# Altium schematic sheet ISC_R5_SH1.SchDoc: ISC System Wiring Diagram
size B; DrawnBy: Filiberto Clara; Engineer: Filiberto Clara; Organization: LIGO Laboratory; Address1: California Institute of Technology; Address2: Massachusetts Institute of Technology; SheetNumber: 19; SheetTotal: 37
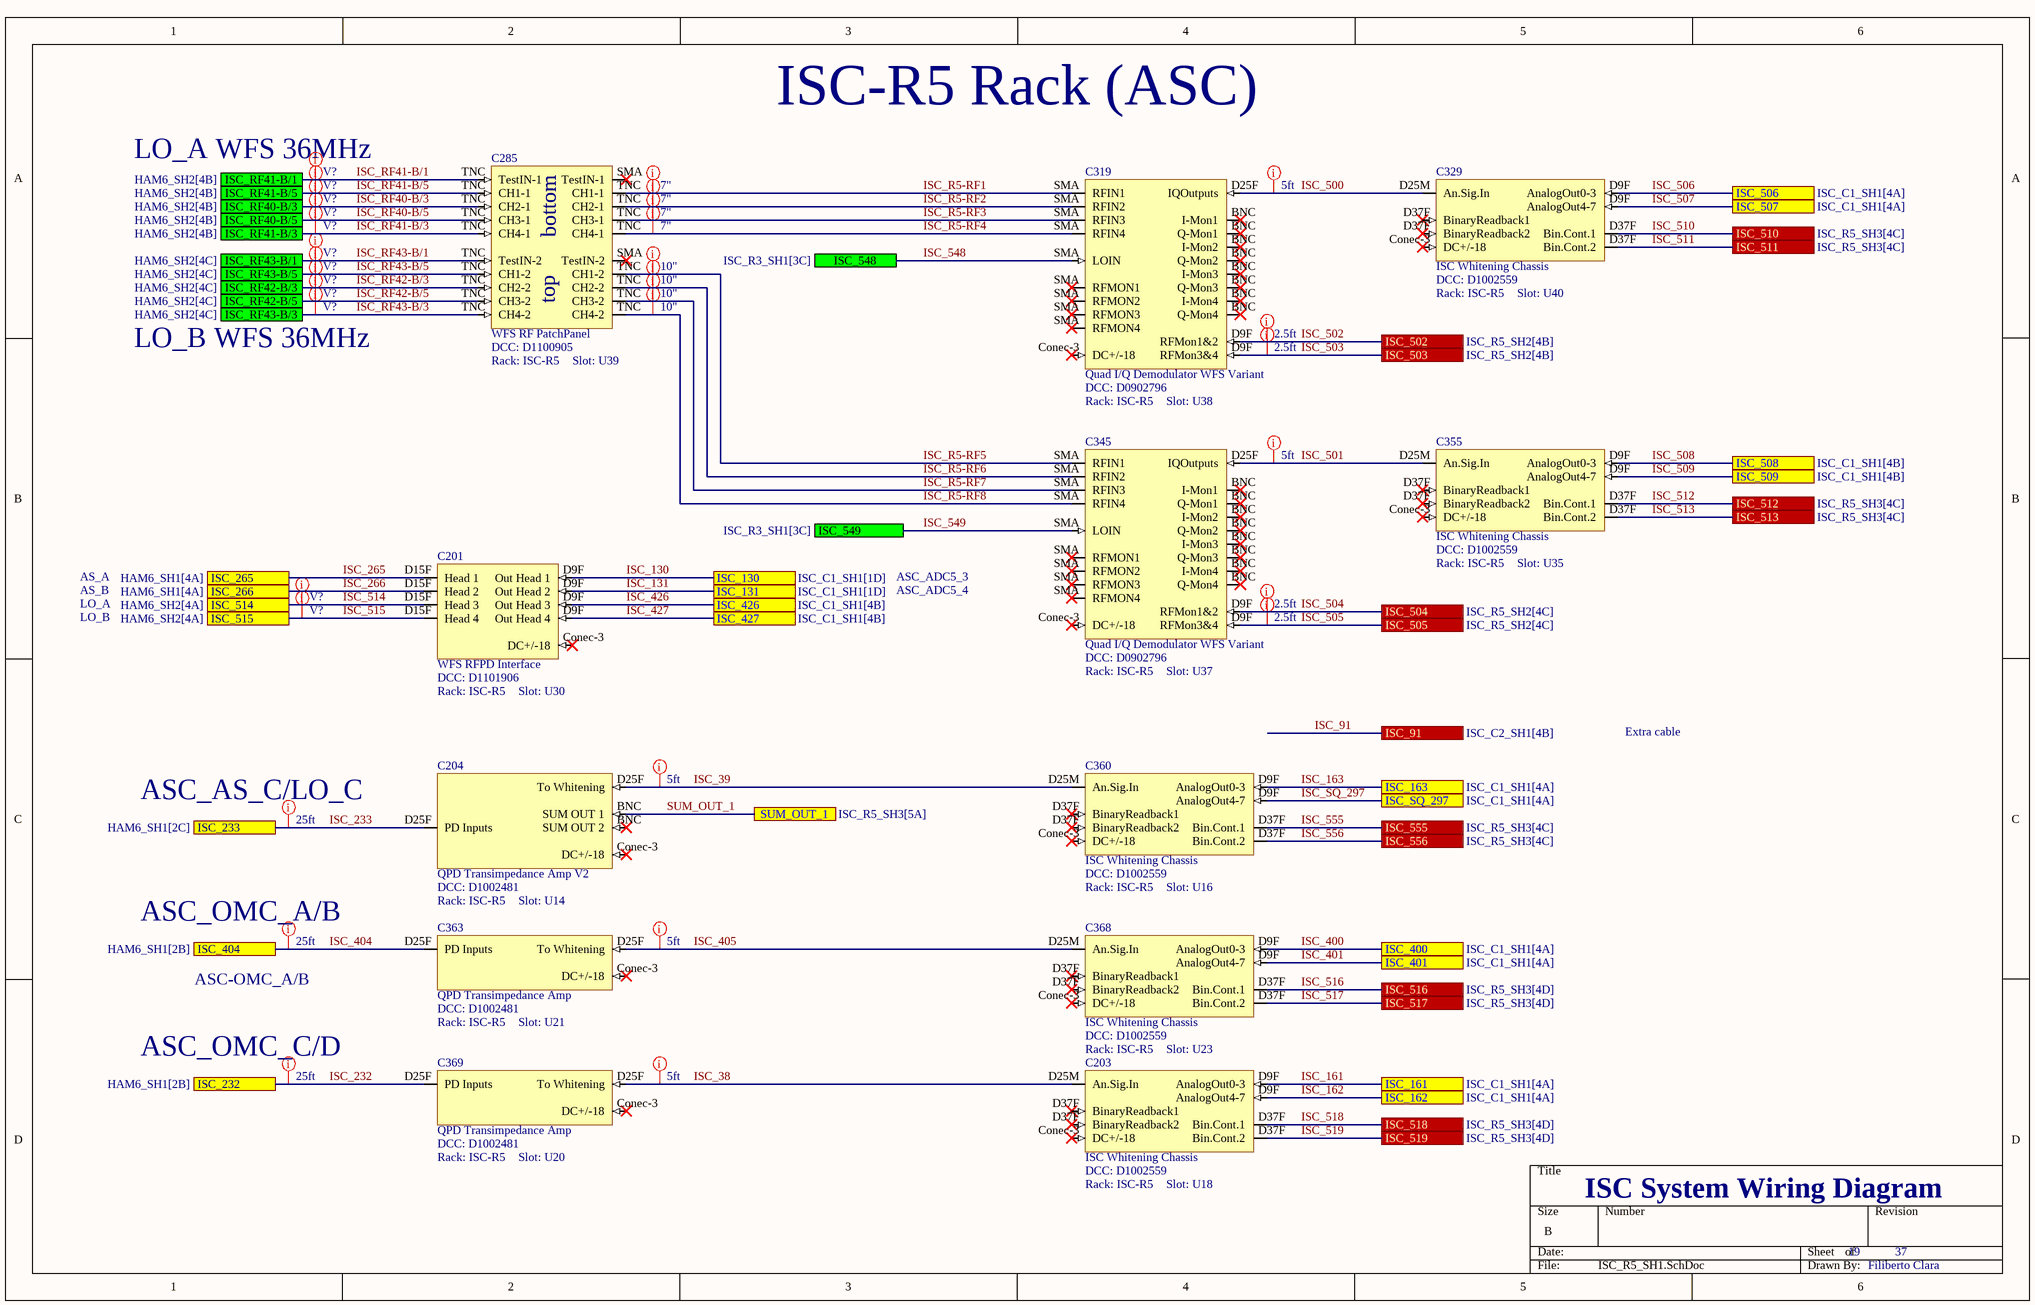
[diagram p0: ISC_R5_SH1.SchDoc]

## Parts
C201  WFS RFPD Interface  DCC: D1101906  Rack: ISC-R5  Slot: U30
C203  ISC Whitening Chassis  DCC: D1002559  Rack: ISC-R5  Slot: U18
C204  QPD Transimpedance Amp V2  DCC: D1002481  Rack: ISC-R5  Slot: U14
C285  WFS RF PatchPanel  DCC: D1100905  Rack: ISC-R5  Slot: U39
C319  Quad I/Q Demodulator WFS Variant  DCC: D0902796  Rack: ISC-R5  Slot: U38
C329  ISC Whitening Chassis  DCC: D1002559  Rack: ISC-R5  Slot: U40
C345  Quad I/Q Demodulator WFS Variant  DCC: D0902796  Rack: ISC-R5  Slot: U37
C355  ISC Whitening Chassis  DCC: D1002559  Rack: ISC-R5  Slot: U35
C360  ISC Whitening Chassis  DCC: D1002559  Rack: ISC-R5  Slot: U16
C363  QPD Transimpedance Amp  DCC: D1002481  Rack: ISC-R5  Slot: U21
C368  ISC Whitening Chassis  DCC: D1002559  Rack: ISC-R5  Slot: U23
C369  QPD Transimpedance Amp  DCC: D1002481  Rack: ISC-R5  Slot: U20

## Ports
ISC_91 (see ISC_C2_SH1[4B]), ISC_130 (see ISC_C1_SH1[1D]), ISC_131 (see ISC_C1_SH1[1D]), ISC_161 (see ISC_C1_SH1[4A]), ISC_162 (see ISC_C1_SH1[4A]), ISC_163 (see ISC_C1_SH1[4A]), ISC_232 (see HAM6_SH1[2B]), ISC_233 (see HAM6_SH1[2C]), ISC_265 (see HAM6_SH1[4A]), ISC_266 (see HAM6_SH1[4A]), ISC_400 (see ISC_C1_SH1[4A]), ISC_401 (see ISC_C1_SH1[4A]), ISC_404 (see HAM6_SH1[2B]), ISC_426 (see ISC_C1_SH1[4B]), ISC_427 (see ISC_C1_SH1[4B]), ISC_502 (see ISC_R5_SH2[4B]), ISC_503 (see ISC_R5_SH2[4B]), ISC_504 (see ISC_R5_SH2[4C]), ISC_505 (see ISC_R5_SH2[4C]), ISC_506 (see ISC_C1_SH1[4A]), ISC_507 (see ISC_C1_SH1[4A]), ISC_508 (see ISC_C1_SH1[4B]), ISC_509 (see ISC_C1_SH1[4B]), ISC_510 (see ISC_R5_SH3[4C]), ISC_511 (see ISC_R5_SH3[4C]), ISC_512 (see ISC_R5_SH3[4C]), ISC_513 (see ISC_R5_SH3[4C]), ISC_514 (see HAM6_SH2[4A]), ISC_515 (see HAM6_SH2[4A]), ISC_516 (see ISC_R5_SH3[4D]), ISC_517 (see ISC_R5_SH3[4D]), ISC_518 (see ISC_R5_SH3[4D]), ISC_519 (see ISC_R5_SH3[4D]), ISC_548 (see ISC_R3_SH1[3C]), ISC_549 (see ISC_R3_SH1[3C]), ISC_555 (see ISC_R5_SH3[4C]), ISC_556 (see ISC_R5_SH3[4C]), ISC_RF40-B/3 (see HAM6_SH2[4B]), ISC_RF40-B/5 (see HAM6_SH2[4B]), ISC_RF41-B/1 (see HAM6_SH2[4B]), ISC_RF41-B/3 (see HAM6_SH2[4B]), ISC_RF41-B/5 (see HAM6_SH2[4B]), ISC_RF42-B/3 (see HAM6_SH2[4C]), ISC_RF42-B/5 (see HAM6_SH2[4C]), ISC_RF43-B/1 (see HAM6_SH2[4C]), ISC_RF43-B/3 (see HAM6_SH2[4C]), ISC_RF43-B/5 (see HAM6_SH2[4C]), ISC_SQ_297 (see ISC_C1_SH1[4A]), SUM_OUT_1 (see ISC_R5_SH3[5A])

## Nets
ISC_38: C203.D25M(An.Sig.In) C369.D25F(To_Whitening)
ISC_39: C204.D25F(To_Whitening) C360.D25M(An.Sig.In)
ISC_130: C201.D9F(Out_Head_1) ; port ISC_130
ISC_131: C201.D9F(Out_Head_2) ; port ISC_131
ISC_161: C203.D9F(AnalogOut0-3) ; port ISC_161
ISC_162: C203.D9F(AnalogOut4-7) ; port ISC_162
ISC_163: C360.D9F(AnalogOut0-3) ; port ISC_163
ISC_232: C369.D25F(PD_Inputs) ; port ISC_232
ISC_233: C204.D25F(PD_Inputs) ; port ISC_233
ISC_265: C201.D15F(Head_1) ; port ISC_265
ISC_266: C201.D15F(Head_2) ; port ISC_266
ISC_400: C368.D9F(AnalogOut0-3) ; port ISC_400
ISC_401: C368.D9F(AnalogOut4-7) ; port ISC_401
ISC_404: C363.D25F(PD_Inputs) ; port ISC_404
ISC_405: C363.D25F(To_Whitening) C368.D25M(An.Sig.In)
ISC_426: C201.D9F(Out_Head_3) ; port ISC_426
ISC_427: C201.D9F(Out_Head_4) ; port ISC_427
ISC_500: C319.D25F(IQOutputs) C329.D25M(An.Sig.In)
ISC_501: C345.D25F(IQOutputs) C355.D25M(An.Sig.In)
ISC_502: C319.D9F(RFMon1&2) ; port ISC_502
ISC_503: C319.D9F(RFMon3&4) ; port ISC_503
ISC_504: C345.D9F(RFMon1&2) ; port ISC_504
ISC_505: C345.D9F(RFMon3&4) ; port ISC_505
ISC_506: C329.D9F(AnalogOut0-3) ; port ISC_506
ISC_507: C329.D9F(AnalogOut4-7) ; port ISC_507
ISC_508: C355.D9F(AnalogOut0-3) ; port ISC_508
ISC_509: C355.D9F(AnalogOut4-7) ; port ISC_509
ISC_510: C329.D37F(BinaryReadback1) ; port ISC_510
ISC_511: C329.D37F(Bin.Cont.2) ; port ISC_511
ISC_512: C355.D37F(BinaryReadback1) ; port ISC_512
ISC_513: C355.D37F(Bin.Cont.2) ; port ISC_513
ISC_514: C201.D15F(Head_3) ; port ISC_514
ISC_515: C201.D15F(Head_4) ; port ISC_515
ISC_516: C368.D37F(BinaryReadback1) ; port ISC_516
ISC_517: C368.D37F(Bin.Cont.2) ; port ISC_517
ISC_518: C203.D37F(BinaryReadback1) ; port ISC_518
ISC_519: C203.D37F(Bin.Cont.2) ; port ISC_519
ISC_548: C319.SMA(LOIN) ; port ISC_548
ISC_549: C345.SMA(LOIN) ; port ISC_549
ISC_555: C360.D37F(BinaryReadback1) ; port ISC_555
ISC_556: C360.D37F(Bin.Cont.2) ; port ISC_556
ISC_R5-RF1: C285.TNC(CH1-1) C319.SMA(RFIN1)
ISC_R5-RF2: C285.TNC(CH2-1) C319.SMA(RFIN2)
ISC_R5-RF3: C285.TNC(CH3-1) C319.SMA(RFIN3)
ISC_R5-RF4: C285.TNC(CH4-1) C319.SMA(RFIN4)
ISC_R5-RF5: C285.TNC(CH1-2) C345.SMA(RFIN1)
ISC_R5-RF6: C285.TNC(CH2-2) C345.SMA(RFIN2)
ISC_R5-RF7: C285.TNC(CH3-2) C345.SMA(RFIN3)
ISC_R5-RF8: C285.TNC(CH4-2) C345.SMA(RFIN4)
ISC_RF40-B/3: C285.TNC(CH2-1) ; port ISC_RF40-B/3
ISC_RF40-B/5: C285.TNC(CH3-1) ; port ISC_RF40-B/5
ISC_RF41-B/1: C285.TNC(TestIN-1) ; port ISC_RF41-B/1
ISC_RF41-B/3: C285.TNC(CH4-1) ; port ISC_RF41-B/3
ISC_RF41-B/5: C285.TNC(CH1-1) ; port ISC_RF41-B/5
ISC_RF42-B/3: C285.TNC(CH2-2) ; port ISC_RF42-B/3
ISC_RF42-B/5: C285.TNC(CH3-2) ; port ISC_RF42-B/5
ISC_RF43-B/1: C285.TNC(TestIN-2) ; port ISC_RF43-B/1
ISC_RF43-B/3: C285.TNC(CH4-2) ; port ISC_RF43-B/3
ISC_RF43-B/5: C285.TNC(CH1-2) ; port ISC_RF43-B/5
ISC_SQ_297: C360.D9F(AnalogOut4-7) ; port ISC_SQ_297
SUM_OUT_1: C204.BNC(SUM_OUT_1) ; port SUM_OUT_1

Not connected (* = marked no-connect by the designer): C201 Conec-3(DC+/-18)*; C203 Conec-3(DC+/-18)*; C204 Conec-3(DC+/-18)*; C285 SMA(TestIN-1)*; C319 BNC(I-Mon1)* Conec-3(DC+/-18)*; C329 Conec-3(DC+/-18)*; C345 BNC(I-Mon1)* Conec-3(DC+/-18)*; C355 Conec-3(DC+/-18)*; C360 Conec-3(DC+/-18)*; C363 Conec-3(DC+/-18)*; C368 Conec-3(DC+/-18)*; C369 Conec-3(DC+/-18)*

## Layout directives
Length: 5ft: ISC_38, ISC_39, ISC_405, ISC_500, ISC_501
Length: 25ft: ISC_232, ISC_233, ISC_404
Length: 10": ISC_R5-RF5, ISC_R5-RF6, ISC_R5-RF7, ISC_R5-RF8
Length: V?: ISC_514, ISC_515, ISC_RF40-B/3, ISC_RF40-B/5, ISC_RF41-B/1, ISC_RF41-B/3, ISC_RF41-B/5, ISC_RF42-B/3, ISC_RF42-B/5, ISC_RF43-B/1, ISC_RF43-B/3, ISC_RF43-B/5
Length: 7": ISC_R5-RF1, ISC_R5-RF2, ISC_R5-RF3, ISC_R5-RF4
Length: 2.5ft: ISC_502, ISC_503, ISC_504, ISC_505

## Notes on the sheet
- ISC-R5 Rack (ASC)
- LO_A WFS 36MHz
- (near C285) bottom
- (near C285) top
- LO_B WFS 36MHz
- AS_A
- ASC_ADC5_3
- AS_B
- LO_A
- LO_B
- ASC_ADC5_4
- Extra cable
- ASC_AS_C/LO_C
- ASC_OMC_A/B
- ASC-OMC_A/B
- ASC_OMC_C/D

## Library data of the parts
C201 = WFS RFPD Interface: Serial: Sxxxxxxx; System: ISC
C203 C329 C355 C360 C368 = ISC Whitening: Serial: Sxxxxxxx
C204 = QPD Transimpedance Amp V2: Serial: Sxxxxxxx; System: ISC
C285 = WFS RFPD PatchPanel: Serial: Sxxxxxxx; System: ISC
C319 C345 = QuadIQdemod_WFS: Serial: Sxxxxxxx; System: ISC
C363 C369 = QPD Transimpedance Amp: Serial: Sxxxxxxx; System: ISC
